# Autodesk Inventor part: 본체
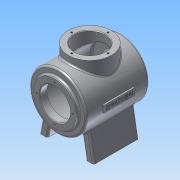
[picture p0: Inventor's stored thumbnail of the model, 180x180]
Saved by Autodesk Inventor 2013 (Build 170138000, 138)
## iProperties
Created: 2015-01
Part Number: 본체
Material: 알루미늄 6061
Document SubType Name: Modeling
Designer: Administrator
Density: 2.71 g/cm^3
Mass: 1021.13 g
Surface Area: 1060.37 cm^2
Volume: 376.8 cm^3
Author: Administrator
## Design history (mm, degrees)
sketch "스케치1"
  geometry: C1 r 50 at (0, 0); 1 further point
  constraints: 1 centre point, 1 coincident
  dimensions: "d0" = 100 diameter of C1
extrude "돌출1" new body sketch "스케치1" stored distance "d1" = 112; taper "d2" = 0 deg
sketch "스케치2"
  geometry: C1 r 50 at (0, 0) reference; C2 r 38 at (0, 0)
  constraints: 1 centre point, 1 coincident
  dimensions: "d3" = 76 diameter of C2
extrude "돌출2" join sketch "스케치2" distance "d4" = 5; taper "d5" = 0 deg
sketch "스케치3"
  geometry: C1 r 50 at (0, 0) reference; C2 r 38 at (0, 0)
  constraints: 1 centre point, 1 coincident
  dimensions: "d6" = 76 diameter of C2
extrude "돌출3" join sketch "스케치3" distance "d7" = 5; taper "d8" = 0 deg
sketch "스케치5"
  geometry: C1 r 38 at (0, 0) reference; C2 r 27 at (0, 0)
  constraints: 1 centre point, 1 coincident
  dimensions: "d12" = 54 diameter of C2
extrude "돌출5" cut sketch "스케치5" stored distance "d13" = 97; taper "d14" = 0 deg
sketch "스케치6"
  geometry: C1 r 27 at (0, 0) reference; 1 further point
  constraints: 1 vertical alignment
  dimensions: "d15" = 32 distance of C1.centre point (0, 32)
hole "구멍1" sketch "스케치6" at (0, 32) diameter "d16" = 3.242; stored, may be unused: countersink angle "d20" = 90 deg, drill point angle "d22" = 118 deg; dims "d17" = 8, "d18" = 4, "d19" = 2, "d21" = 10
sketch "스케치7"
  geometry: L1 (-48, -80)-(-34, -80); L2 (-39.336, -30.865)-(-48, -80); L3 (-34, -80)-(-27.282, -41.901); C1 r 38 at (0, 0) reference; A1 r 50 centre (0, 0) between (-39.336, -30.865) and (-27.282, -41.901) reference; A2 r 50 centre (0, 0) between (-39.336, -30.865) and (-27.282, -41.901) reference; 1 further point
  constraints: 6 end point, 4 point on circle, 1 horizontal
  dimensions: "d26" = 80 distance from line of point (0, 0) L1; "d28" = 80 deg angle of L1 L3; "d29" = 100 deg angle of L1 L2; "d30" = 14 distance of L1.end L1.start; "d31" = 48 horizontal distance of point (0, 0) L1.start
feature "리브1" sketch "스케치7" dims "d32" = 1, "d33" = 80, "d34" = 0, "d35" = 0, "d36" = 1, "d37" = 1
node "작업 평면1"
node "작업 평면5"
  node "작업 평면4"
sketch "스케치13"
  geometry: L1 (6, 26)-(-6, 26); L2 (-6, 26)-(-6, -28); L3 (-6, -28)-(6, -28); L4 (6, -28)-(6, 26); L5 (62, 37)-(62, -39) reference; L6 (38, 61)-(-38, 61) reference; 2 further points
  constraints: 8 end point, 2 parallel, 1 horizontal, 1 midpoint, 1 perpendicular, 1 vertical alignment
  dimensions: "d75" = 54 distance of L3.end L1.start; "d77" = 12 distance of L1.start L1.end; "d78" = 35 distance between parallel lines of L1 L6
extrude "돌출9" join sketch "스케치13" stored distance "d79" = 97; taper "d80" = 0 deg
sketch "스케치14"
  geometry: L1 (-61, 38)-(-61, -38) reference; 2 further points
  constraints: 1 horizontal alignment, 1 other
  dimensions: "d81" = 62 distance from line of L1 point (1, 0)
feature "엠보싱1" sketch "스케치14" dims "d14" = 0, "d82" = 0.5, "d83" = 0
fillet "모깎기1" dims "d101" = 3
fillet "모깎기2" dims "d102" = 3
chamfer "모따기1" distance "d103" = 1; stored, may be unused: second distance "d104" = 2, angle "d105" = 45 deg
node "작업 평면6"
sketch "스케치18"
  geometry: C1 r 50 at (0, 0) reference; C2 r 45 at (0, 0); 1 further point
  constraints: 1 centre point, 1 coincident
  dimensions: "d107" = 90 diameter of C2
extrude "돌출12" cut sketch "스케치18" distance "d108" = 49; taper "d109" = 0 deg; dims "d110" = 48, "d111" = 0
sketch "스케치19"
  geometry: L1 (38, 61)-(-38, 61) reference; C1 r 38 at (0, -1); 1 further point
  constraints: 1 centre point, 1 vertical alignment
  dimensions: "d112" = 76 diameter of C1; "d113" = 62 distance from line of C1.centre L1
extrude "돌출13" join sketch "스케치19" stored distance "d114" = 48.5; taper "d115" = 0 deg
sketch "스케치20"
  geometry: C1 r 38 at (0, 0) reference; C2 r 27 at (0, 0); 1 further point
  constraints: 1 centre point, 1 coincident
  dimensions: "d116" = 54 diameter of C2
extrude "돌출14" cut sketch "스케치20" stored distance "d117" = 48.5; taper "d118" = 0 deg
sketch "스케치21"
  geometry: C1 r 27 at (0, 0) reference; 2 further points
  constraints: 1 vertical alignment
  dimensions: "d119" = 32 distance of C1.centre point (0, 32)
hole "구멍5" sketch "스케치21" at (0, 32) diameter "d120" = 3.242; stored, may be unused: countersink angle "d124" = 90 deg, drill point angle "d126" = 118 deg; dims "d121" = 8, "d122" = 4, "d123" = 2, "d125" = 10
fillet "모깎기3" dims "d130" = 3
chamfer "모따기2" distance "d131" = 1; stored, may be unused: second distance "d132" = 2, angle "d133" = 45 deg
node "솔리드1"
pattern_circular "원형 패턴1" dims angle "d24" = 360 deg
mirror "대칭1"
mirror "대칭2"
pattern_circular "원형 패턴5" dims angle "d128" = 360 deg
node "투영된 루프2"
other parameters: "d38" = 62, "d74" = 2, "d106" = -62
